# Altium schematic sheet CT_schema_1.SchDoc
size 811 x 486 mm
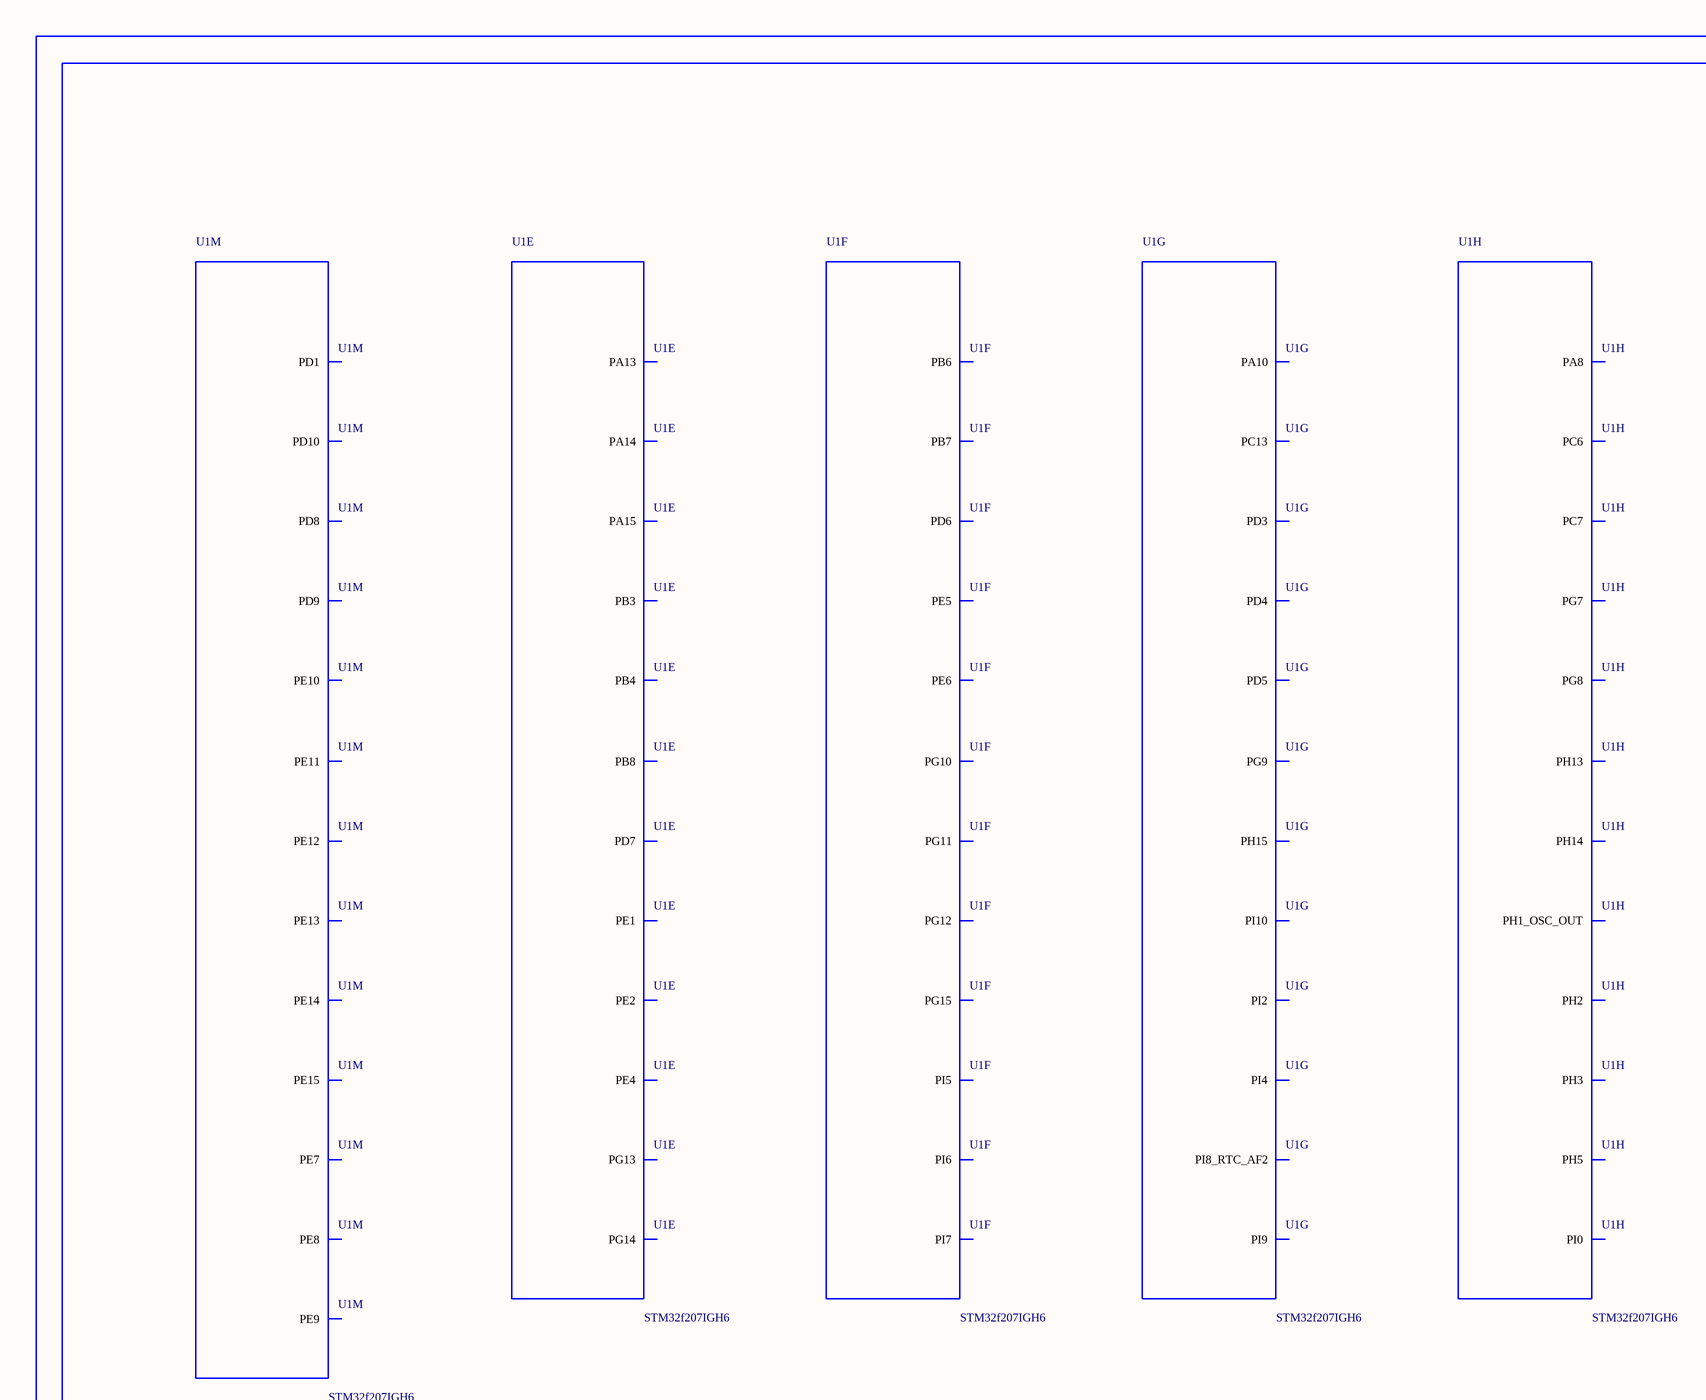
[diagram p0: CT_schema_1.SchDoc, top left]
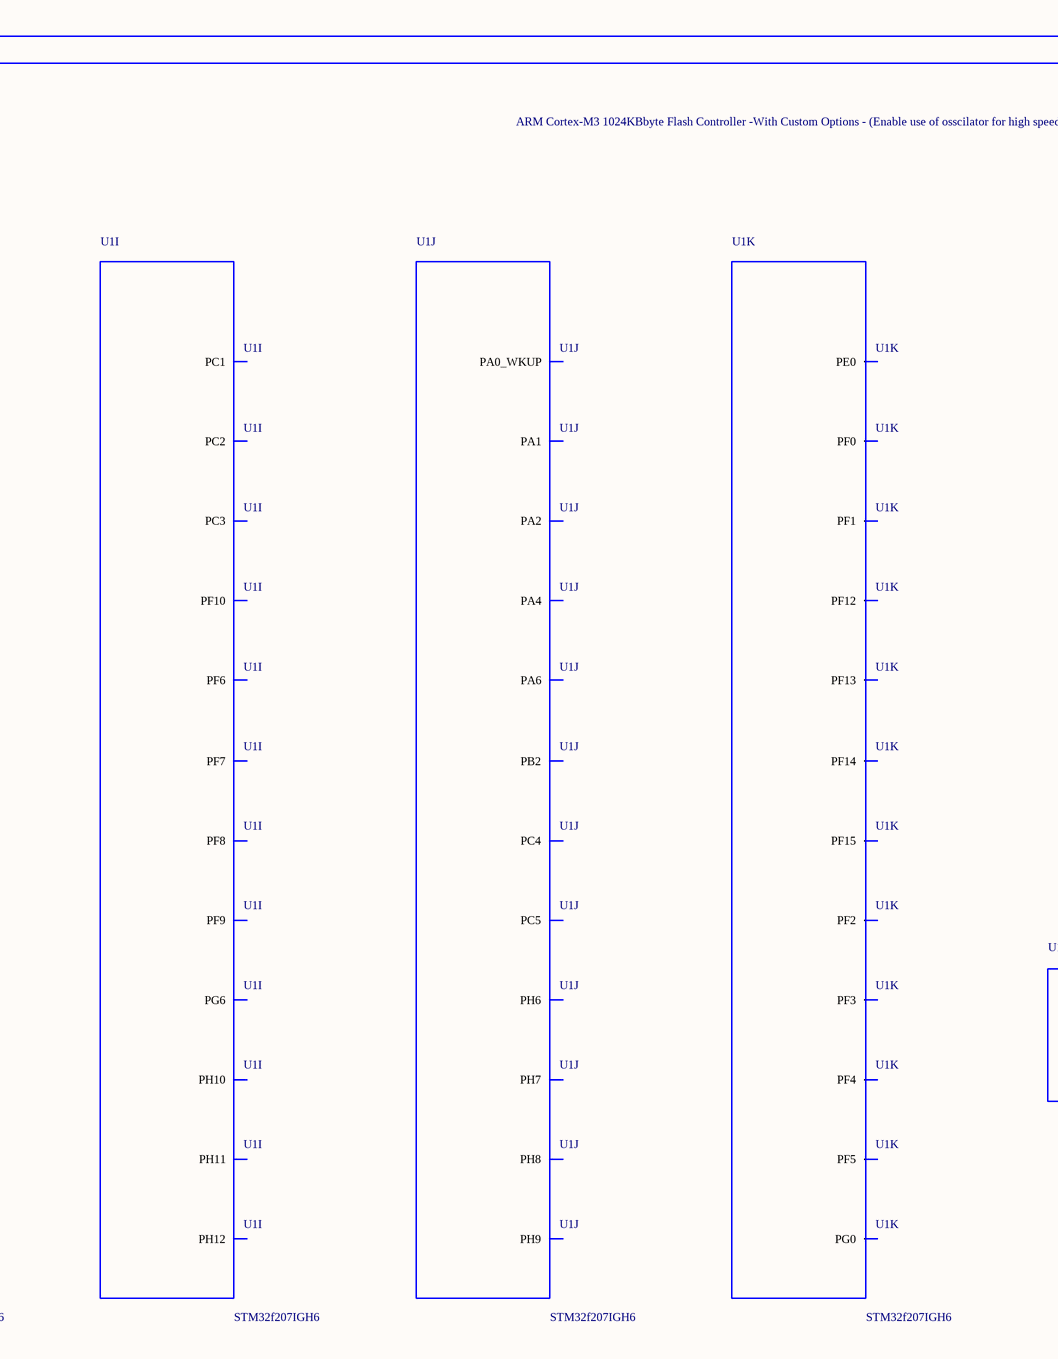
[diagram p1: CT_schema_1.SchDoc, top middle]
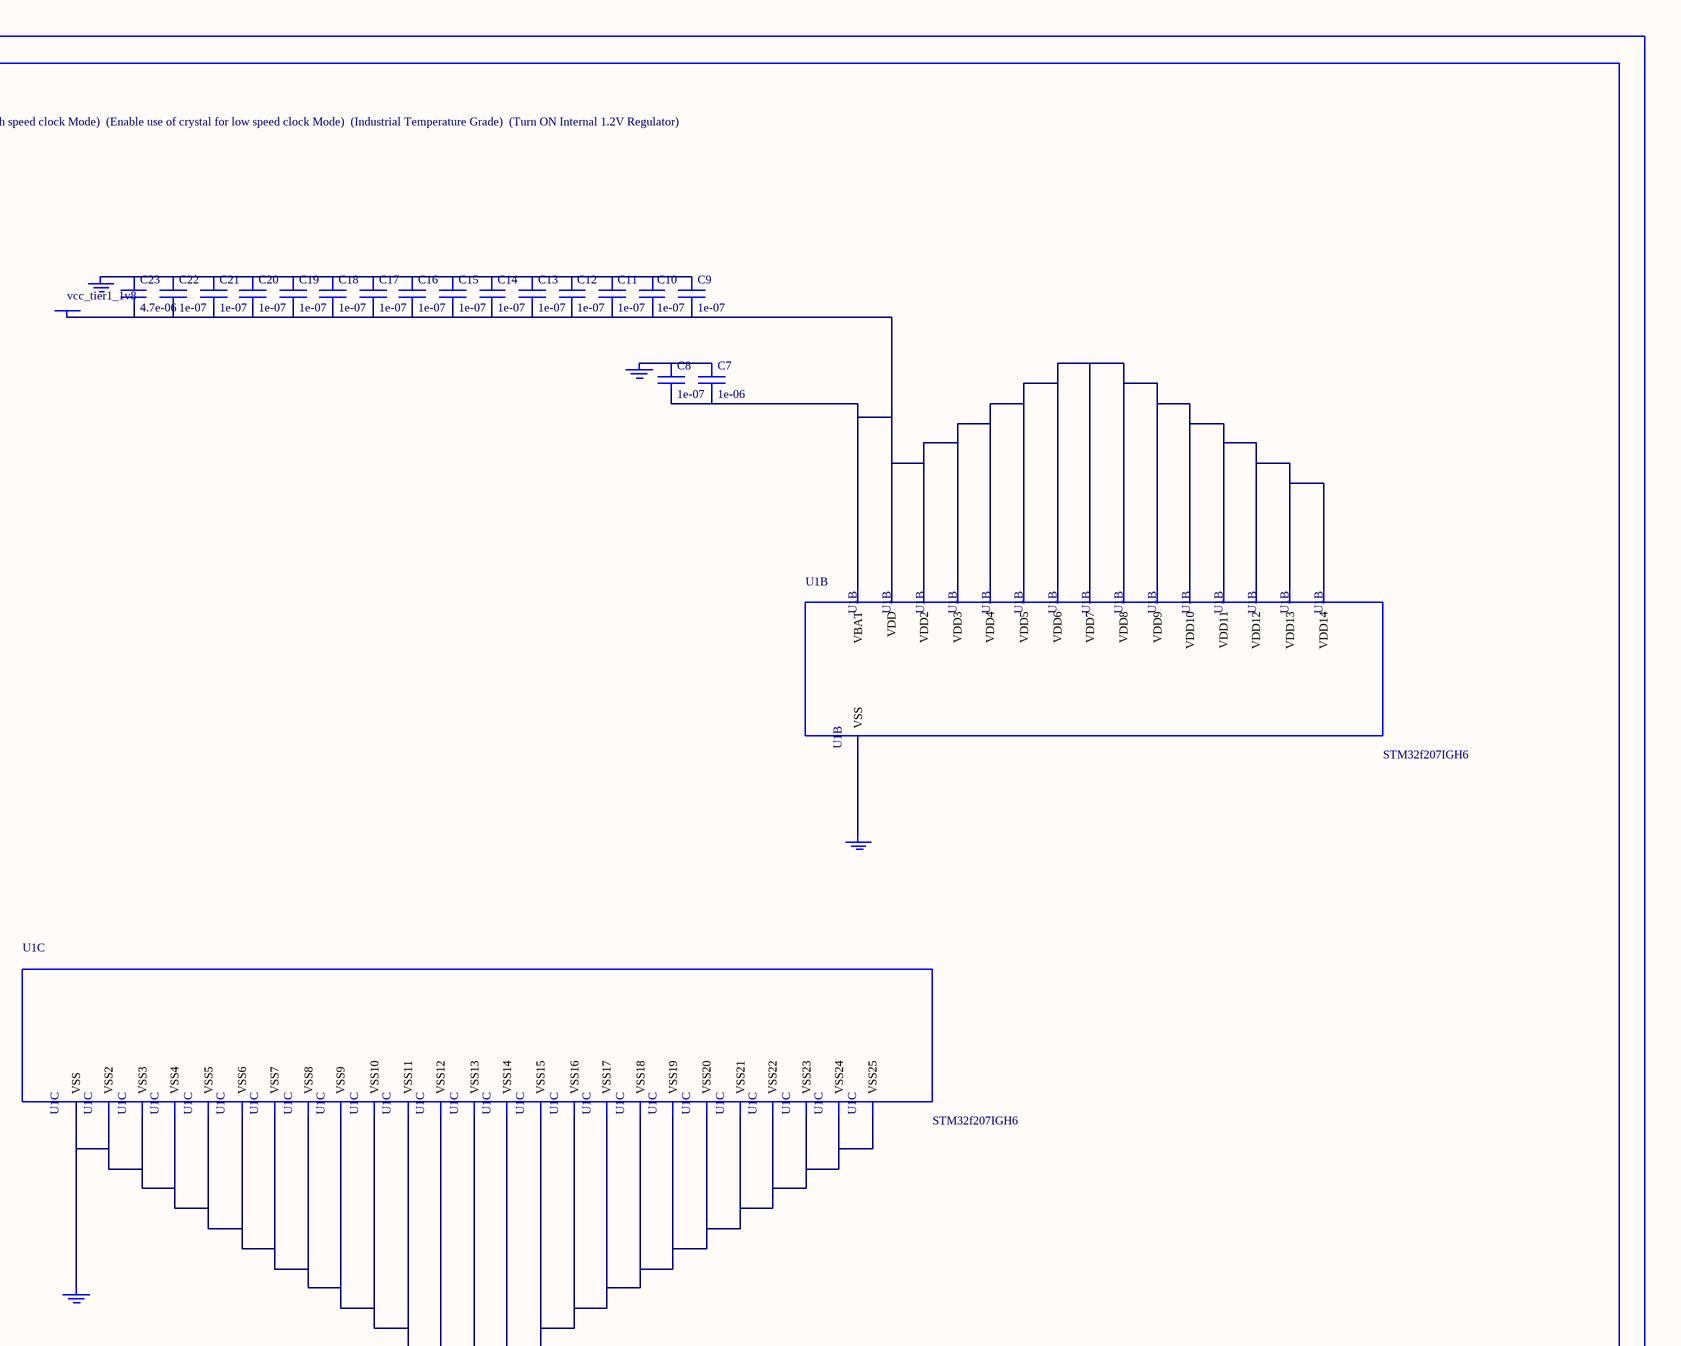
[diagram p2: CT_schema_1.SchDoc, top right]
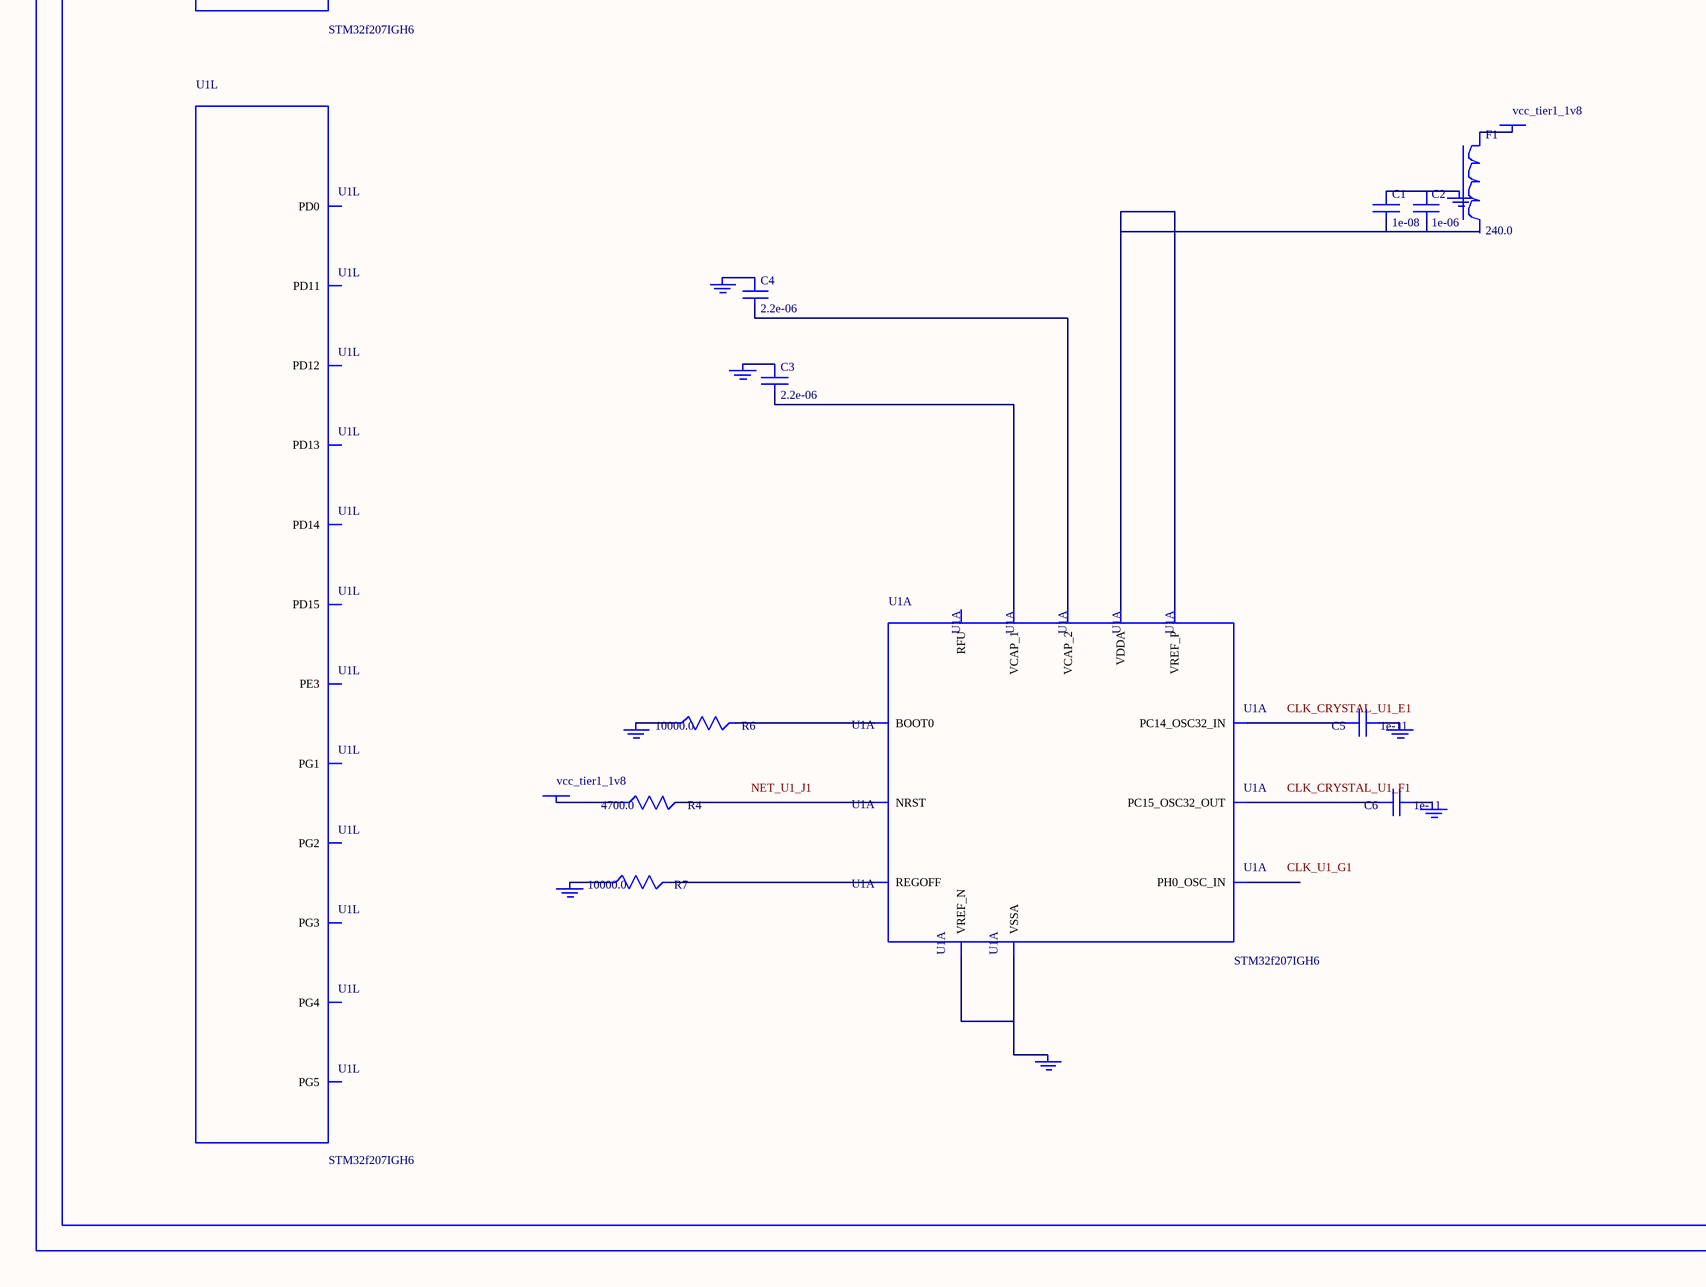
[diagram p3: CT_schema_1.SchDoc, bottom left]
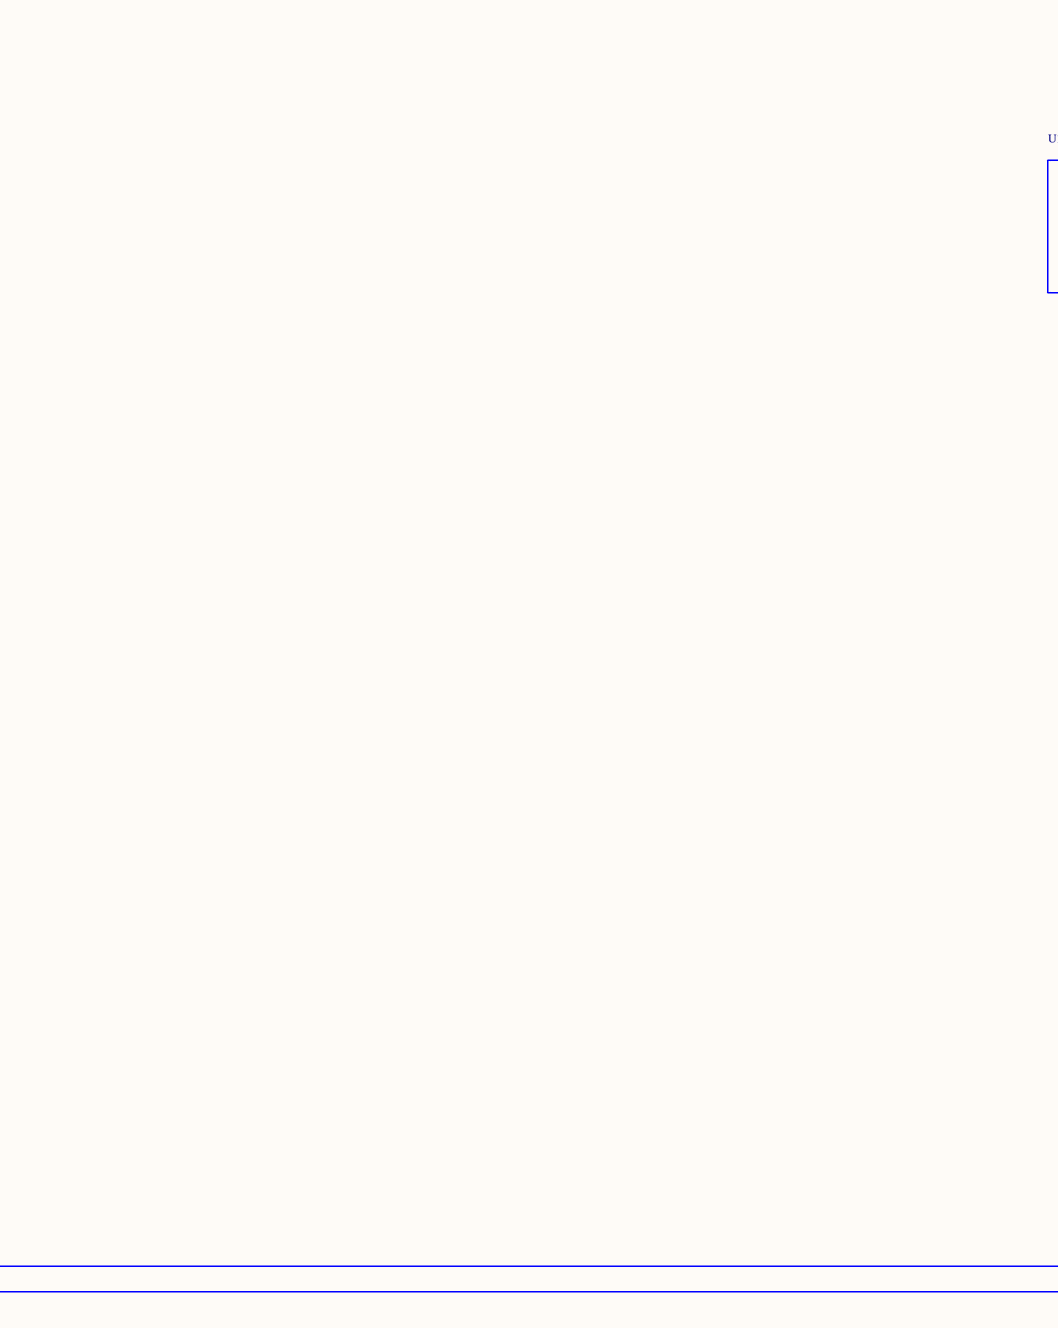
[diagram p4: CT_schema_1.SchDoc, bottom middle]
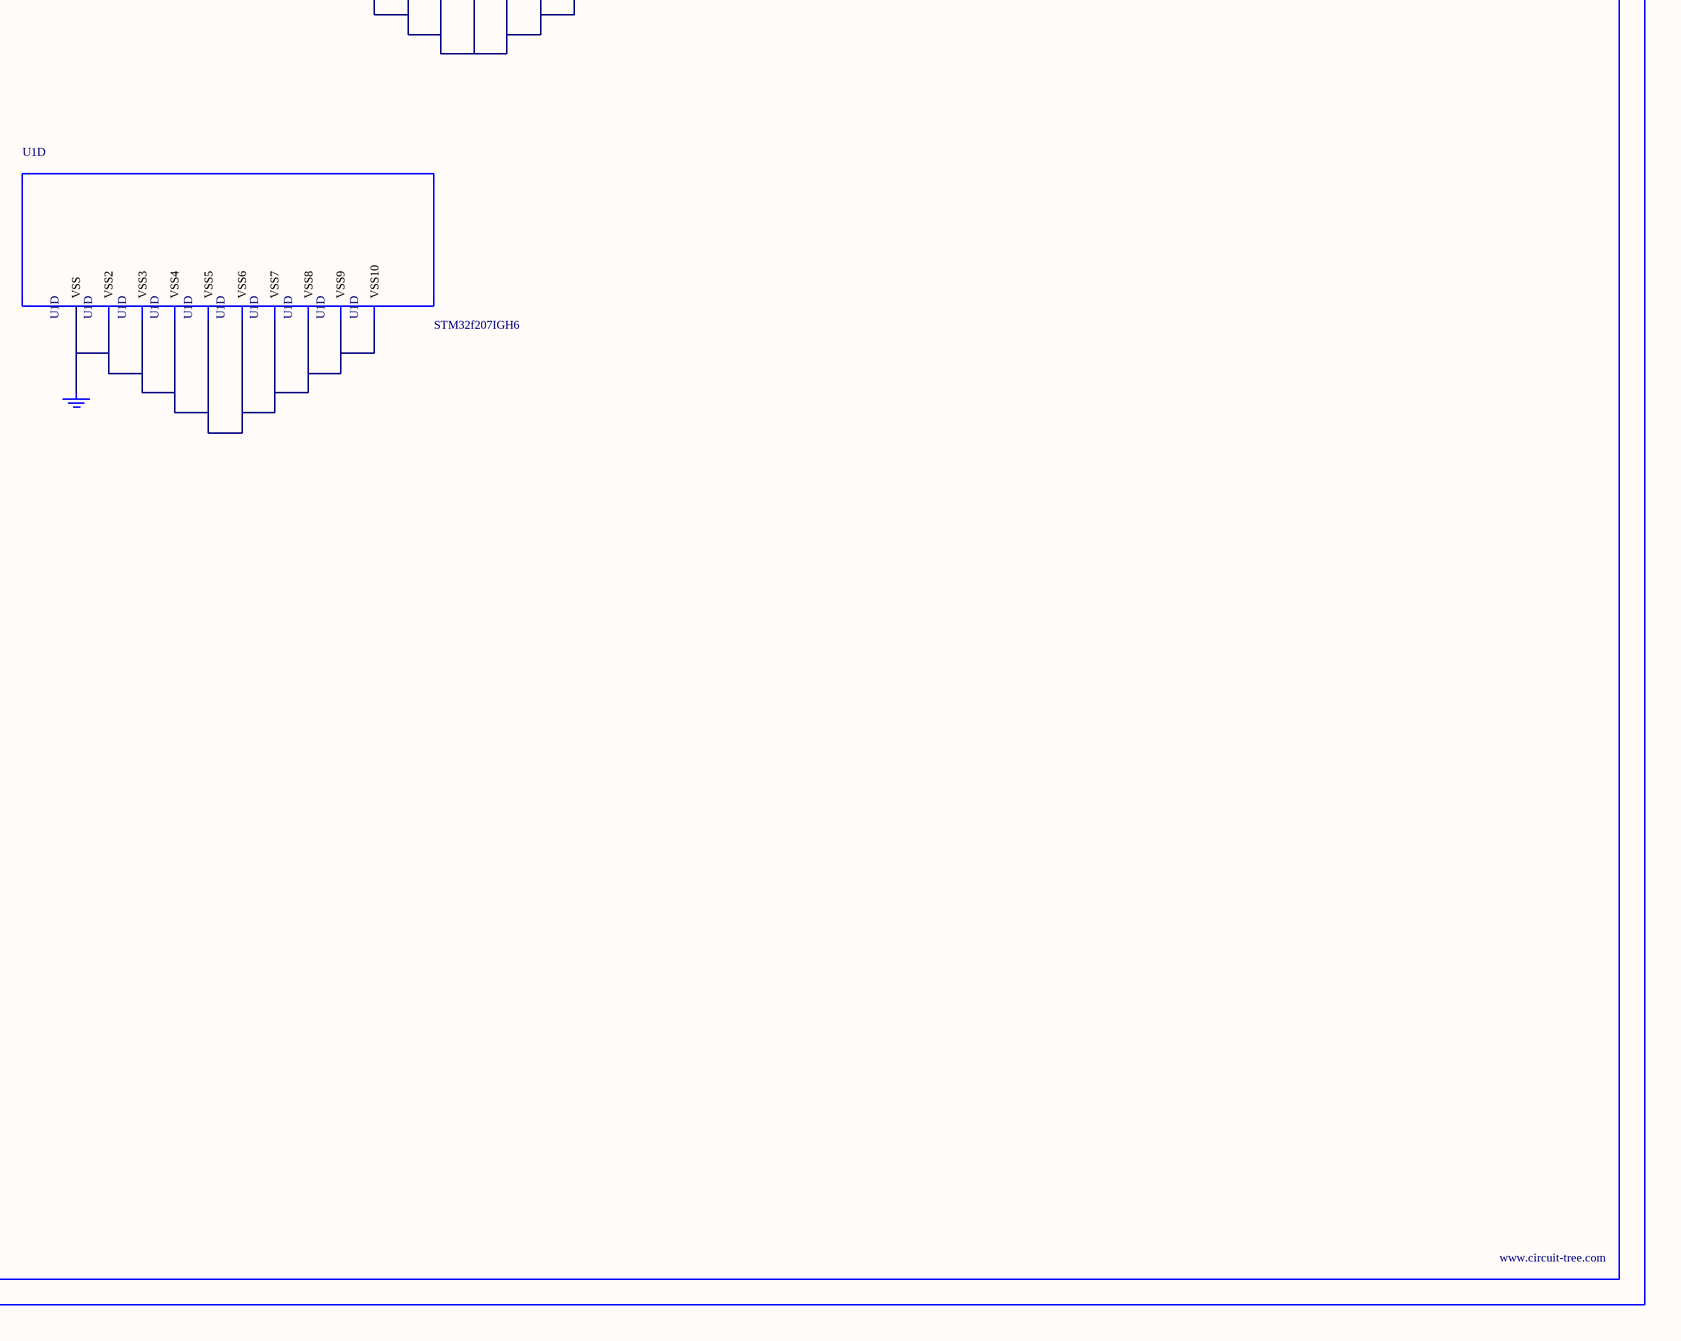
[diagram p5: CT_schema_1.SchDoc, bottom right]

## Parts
BORDER0  (no value)
C1  1e-08  [C0603]
C2  1e-06  [C0603]
C3  2.2e-06  [C0603]
C4  2.2e-06  [C0603]
C5  1e-11  [C0402]
C6  1e-11  [C0402]
C7  1e-06  [C0603]
C8  1e-07  [C0603]
C9  1e-07  [C0603]
C10  1e-07  [C0603]
C11  1e-07  [C0603]
C12  1e-07  [C0603]
C13  1e-07  [C0603]
C14  1e-07  [C0603]
C15  1e-07  [C0603]
C16  1e-07  [C0603]
C17  1e-07  [C0603]
C18  1e-07  [C0603]
C19  1e-07  [C0603]
C20  1e-07  [C0603]
C21  1e-07  [C0603]
C22  1e-07  [C0603]
C23  4.7e-06  [C0603]
F1  240.0  [L0603]
GND_INSTANCE_0_0  (no value)
GND_INSTANCE_0_1  (no value)
GND_INSTANCE_0_2  (no value)
GND_INSTANCE_0_3  (no value)
GND_INSTANCE_0_4  (no value)
GND_INSTANCE_0_5  (no value)
GND_INSTANCE_0_6  (no value)
GND_INSTANCE_0_7  (no value)
GND_INSTANCE_0_8  (no value)
GND_INSTANCE_0_9  (no value)
GND_INSTANCE_0_10  (no value)
GND_INSTANCE_0_11  (no value)
GND_INSTANCE_0_12  (no value)
POWER_INSTANCE_0_0  vcc_tier1_1v8
POWER_INSTANCE_0_1  vcc_tier1_1v8
POWER_INSTANCE_0_2  vcc_tier1_1v8
R4  4700.0  [R0603]
R6  10000.0  [R0603]
R7  10000.0  [R0603]
U1  STM32f207IGH6  [UFBGA176_25]  (parts A,B,C,D,E,F,G,H,I,J,K,L,M of 16)

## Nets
NetC1_1: C1.1 C2.1 GND_INSTANCE_0_0.0(GND)
NetC1_2: C1.2 C2.2 U1.P1(VREF_P) U1.R1(VDDA)
NetC3_1: C3.1 GND_INSTANCE_0_3.0(GND)
NetC3_2: C3.2 U1.M10(VCAP_1)
NetC4_1: C4.1 GND_INSTANCE_0_4.0(GND)
NetC4_2: C4.2 U1.F13(VCAP_2)
NetC5_1: C5.1 GND_INSTANCE_0_5.0(GND)
NetC5_2: C5.2 U1.E1(PC14_OSC32_IN)
NetC6_1: C6.1 GND_INSTANCE_0_6.0(GND)
NetC6_2: C6.2 U1.F1(PC15_OSC32_OUT)
NetC7_1: C7.1 C8.1 GND_INSTANCE_0_8.0(GND)
NetC7_2: C7.2 C8.2 C9.2 C10.2 C11.2 C12.2 C13.2 C14.2 C15.2 C16.2 C17.2 C18.2 C19.2 C20.2 C21.2 C22.2 C23.2 POWER_INSTANCE_0_2.0(PWR) U1.C1(VBAT) U1.C5(VDD) U1.C7(VDD2) U1.C8(VDD3) U1.C9(VDD4) U1.F3(VDD5) U1.G3(VDD7) U1.G13(VDD6) U1.H13(VDD8) U1.J12(VDD9) U1.J13(VDD10) U1.K4(VDD11) U1.N8(VDD13) U1.N9(VDD14) U1.N10(VDD12)
NetC9_1: C9.1 C10.1 C11.1 C12.1 C13.1 C14.1 C15.1 C16.1 C17.1 C18.1 C19.1 C20.1 C21.1 C22.1 C23.1 GND_INSTANCE_0_9.0(GND)
NetF1_1: F1.1 POWER_INSTANCE_0_0.0(PWR)
NetGND_INSTANCE_0_1_0: GND_INSTANCE_0_1.0(GND) R6.1
NetGND_INSTANCE_0_2_0: GND_INSTANCE_0_2.0(GND) R7.1
NetGND_INSTANCE_0_7_0: GND_INSTANCE_0_7.0(GND) U1.M1(VSSA) U1.N1(VREF_N)
NetGND_INSTANCE_0_10_0: GND_INSTANCE_0_10.0(GND) U1.D5(VSS)
NetGND_INSTANCE_0_11_0: GND_INSTANCE_0_11.0(GND) U1.D7(VSS) U1.D8(VSS2) U1.D9(VSS3) U1.F2(VSS6) U1.F6(VSS7) U1.F7(VSS8) U1.F8(VSS9) U1.F9(VSS10) U1.F10(VSS4) U1.F12(VSS5) U1.G2(VSS13) U1.G6(VSS14) U1.G7(VSS15) U1.G8(VSS16) U1.G9(VSS17) U1.G10(VSS11) U1.G12(VSS12) U1.H6(VSS20) U1.H7(VSS21) U1.H8(VSS22) U1.H9(VSS23) U1.H10(VSS18) U1.H12(VSS19) U1.J6(VSS25) U1.J10(VSS24)
NetGND_INSTANCE_0_12_0: GND_INSTANCE_0_12.0(GND) U1.J7(VSS) U1.J8(VSS2) U1.J9(VSS3) U1.K6(VSS5) U1.K7(VSS6) U1.K8(VSS7) U1.K9(VSS8) U1.K10(VSS4) U1.M8(VSS9) U1.M9(VSS10)
NetPOWER_INSTANCE_0_1_0: POWER_INSTANCE_0_1.0(PWR) R4.1
NetR4_2: R4.2 U1.J1(NRST)
NetR6_2: R6.2 U1.D6(BOOT0)
NetR7_2: R7.2 U1.L4(REGOFF)

Not connected (* = marked no-connect by the designer): F1 2; U1 A1(PE3) A2(PE2) A3(PE1) A4(PE0) A5(PB8) A7(PG14) A8(PG13) A9(PB4) A10(PB3) A11(PD7) A13(PA15) A14(PA14) A15(PA13) B1(PE4) B2(PE5) B3(PE6) B5(PB7) B6(PB6) B7(PG15) B8(PG12) B9(PG11) B10(PG10) B11(PD6) B12(PD0) C2(PI7) C3(PI6) C4(PI5) C6(RFU) C10(PG9) C11(PD5) C12(PD1) C14(PI2) D1(PC13) D2(PI8_RTC_AF2) D3(PI9) D4(PI4) D10(PD4) D11(PD3) D13(PH15) D15(PA10) E2(PF0) E3(PI10) E12(PH13) E13(PH14) E14(PI0) F4(PH2) F15(PA8) G1(PH0_OSC_IN) G4(PH3) G15(PC7) H1(PH1_OSC_OUT) H2(PF2) H3(PF1) H14(PG8) H15(PC6) J2(PF3) J3(PF4) J4(PH5) J14(PG7) J15(PG6) K1(PF7) K2(PF6) K3(PF5) K12(PH12) K13(PG5) K14(PG4) K15(PG3) L1(PF10) L2(PF9) L3(PF8) L12(PH11) L13(PH10) L14(PD15) L15(PG2) M3(PC1) M4(PC2) M5(PC3) M6(PB2) M7(PG1) M11(PH6) M12(PH8) M13(PH9) M14(PD14) M15(PD13) N2(PA1) N3(PA0_WKUP) N4(PA4) N5(PC4) N6(PF13) N7(PG0) N11(PE13) N12(PH7) N13(PD12) N14(PD11) N15(PD10) P2(PA2) P3(PA6) P5(PC5) P6(PF12) P7(PF15) P8(PE8) P9(PE9) P10(PE11) P11(PE14) P14(PD9) P15(PD8) R7(PF14) R8(PE7) R9(PE10) R10(PE12) R11(PE15)

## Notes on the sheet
- Labels drawn without touching a wire or pin: CLK_CRYSTAL_U1_E1, CLK_CRYSTAL_U1_F1, CLK_U1_G1, NET_U1_J1

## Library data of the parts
BORDER0 = BORDER_PAGE0
C1 = 06035C103K4Z2A
C2 C7 = C0603C105K3RACTU
C3 C4 = C0603C225K8RACTU
C5 C6 = C0402C100K3GACTU
C8-C22 = 06035C104K4Z2A
C23 = GRM188R6YA475KE15D
F1 = Z0603C241ASMST
GND_INSTANCE_0_0-GND_INSTANCE_0_12 = GND
POWER_INSTANCE_0_0-POWER_INSTANCE_0_2 = PWR
R4 = RC0603JR-074K7L
R6 R7 = RC0603JR-0710KL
